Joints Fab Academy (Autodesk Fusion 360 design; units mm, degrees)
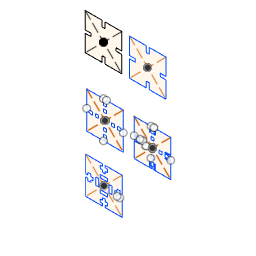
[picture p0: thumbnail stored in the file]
sketch "Joints Fab Academy"
  line L1 (132.7667, 45.561) -> (132.7667, 38.008)
  line L2 (132.0608, 36.2433) -> (132.2373, 36.4551)
  line L3 (123.5373, 64.2908) -> (123.8903, 64.3614)
  line L4 (132.4138, 36.7021) -> (132.555, 36.9139)
  line L5 (120.802, 48.8786) -> (120.802, 48.1374)
  line L6 (120.802, 48.1374) -> (116.9903, 48.1374)
  line L7 (127.8608, 48.0315) -> (123.202, 48.7727)
  line L8 (116.9903, 50.2904) -> (113.9903, 50.2904)
  line L9 (134.8314, 64.8202) -> (134.8314, 64.9614)
  line L10 (113.9903, 50.2904) -> (113.9903, 53.608)
  line L11 (122.9197, 28.1963) -> (122.7785, 28.3374)
  line L12 (123.0608, 28.0551) -> (122.9197, 28.1963)
  line L13 (123.1667, 27.8786) -> (123.0608, 28.0551)
  line L14 (116.9903, 24.3492) -> (116.9903, 26.0433)
  line L15 (132.2373, 36.4551) -> (132.4138, 36.7021)
  line L16 (122.5314, 34.6904) -> (121.9314, 34.6551)
  line L17 (113.0902, 73.8555) -> (113.0902, 81.2672)
  line L18 (115.3844, 83.8084) -> (115.6314, 83.8084)
  line L19 (125.1255, 84.7261) -> (125.1255, 84.6908)
  line L20 (125.055, 84.7261) -> (125.1255, 84.7261)
  line L21 (124.8785, 84.7614) -> (125.055, 84.7261)
  line L22 (118.0314, 83.8084) -> (122.9373, 84.5849)
  line L23 (116.9903, 29.961) -> (113.9903, 29.961)
  line L24 (131.1432, 35.6786) -> (131.3903, 35.7845)
  line L25 (132.7667, 37.7257) -> (132.7667, 38.008)
  line L26 (130.3314, 35.5374) -> (130.6138, 35.5374)
  line L27 (116.9903, 33.2786) -> (116.9903, 35.4316)
  line L28 (123.202, 34.7963) -> (122.5314, 34.6904)
  line L29 (135.4667, 80.6672) -> (135.4314, 80.7378)
  line L30 (135.4667, 80.5614) -> (135.4667, 80.6672)
  line L31 (135.0079, 81.5849) -> (134.9373, 81.8319)
  line L32 (135.0785, 81.3731) -> (135.0079, 81.5849)
  line L33 (135.2903, 80.9496) -> (135.0785, 81.3731)
  line L34 (135.4314, 80.7378) -> (135.2903, 80.9496)
  line L35 (132.5373, 80.632) -> (132.6432, 80.7378)
  line L36 (132.3961, 80.5614) -> (132.5373, 80.632)
  line L37 (133.702, 89.7378) -> (133.7373, 89.5614)
  line L38 (135.2197, 80.279) -> (135.3255, 80.3143)
  line L39 (135.1138, 80.279) -> (135.2197, 80.279)
  line L40 (135.0432, 80.3143) -> (135.1138, 80.279)
  line L41 (134.9373, 80.3849) -> (135.0432, 80.3143)
  line L42 (113.9903, 33.2786) -> (113.9903, 29.961)
  line L43 (122.5314, 48.8433) -> (121.9314, 48.9139)
  line L44 (132.7667, 45.8433) -> (132.7667, 45.561)
  line L45 (123.202, 48.7727) -> (122.5314, 48.8433)
  line L46 (116.9903, 50.2904) -> (116.9903, 48.1374)
  line L47 (116.9903, 59.2198) -> (116.9903, 57.5257)
  line L48 (132.255, 74.5966) -> (132.1138, 74.632)
  line L49 (135.2903, 74.1731) -> (135.4314, 74.3849)
  line L50 (132.7314, 46.1257) -> (132.7667, 45.8433)
  line L51 (121.9314, 48.9139) -> (121.5079, 48.9492)
  line L52 (135.1138, 61.8202) -> (134.8314, 61.8202)
  line L53 (131.8314, 65.632) -> (131.8314, 65.7731)
  line L54 (121.1197, 48.9139) -> (120.802, 48.8786)
  line L55 (130.3314, 35.5374) -> (127.8608, 35.5374)
  line L56 (123.0079, 70.5378) -> (122.9373, 70.5378)
  line L57 (134.902, 74.6672) -> (134.8667, 74.5966)
  line L58 (136.4726, 24.3492) -> (136.4726, 59.2198)
  line L59 (136.4726, 59.2198) -> (116.9903, 59.2198)
  line L60 (113.1255, 73.5731) -> (113.0902, 73.8555)
  line L61 (121.5079, 48.9492) -> (121.1197, 48.9139)
  line L62 (137.3726, 91.0084) -> (137.3726, 90.7261)
  line L63 (123.2726, 27.1021) -> (123.3079, 27.3139)
  line L64 (116.9903, 26.0433) -> (122.0373, 26.0433)
  line L65 (123.2373, 26.9257) -> (123.2726, 27.1021)
  line L66 (123.1667, 26.7139) -> (123.2373, 26.9257)
  line L67 (122.9197, 26.3963) -> (123.0608, 26.5727)
  line L68 (122.7785, 26.2904) -> (122.9197, 26.3963)
  line L69 (123.0608, 26.5727) -> (123.1667, 26.7139)
  line L70 (131.3903, 35.7845) -> (131.6373, 35.9257)
  line L71 (130.8608, 35.608) -> (131.1432, 35.6786)
  line L72 (136.4726, 24.3492) -> (116.9903, 24.3492)
  line L73 (132.7314, 37.4433) -> (132.7667, 37.7257)
  line L74 (131.3903, 47.7845) -> (131.6373, 47.6433)
  line L75 (123.2373, 27.7021) -> (123.1667, 27.8786)
  line L76 (132.555, 46.6198) -> (132.6608, 46.3727)
  line L77 (120.802, 35.4316) -> (116.9903, 35.4316)
  line L78 (132.555, 36.9139) -> (132.6608, 37.1963)
  line L79 (122.4255, 28.5139) -> (122.2138, 28.5492)
  line L80 (122.2138, 28.5492) -> (122.0373, 28.5845)
  line L81 (120.802, 34.6551) -> (120.802, 35.4316)
  line L82 (123.2726, 27.4904) -> (123.2373, 27.7021)
  line L83 (123.3079, 27.3139) -> (123.2726, 27.4904)
  line L84 (126.7314, 15.6908) -> (123.7314, 15.6908)
  line L85 (131.8844, 21.3025) -> (131.8844, -16.321)
  line L86 (118.5785, 21.3025) -> (131.8844, 21.3025)
  line L87 (118.5785, -16.321) -> (118.5785, 21.3025)
  line L88 (131.8844, -16.321) -> (118.5785, -16.321)
  line L89 (116.9903, 54.9845) -> (116.9903, 53.608)
  line L90 (122.2138, 54.9845) -> (122.0373, 54.9845)
  line L91 (122.4255, 55.0551) -> (122.2138, 54.9845)
  line L92 (122.602, 55.1257) -> (122.4255, 55.0551)
  line L93 (122.7785, 55.2315) -> (122.602, 55.1257)
  line L94 (122.9197, 55.3727) -> (122.7785, 55.2315)
  line L95 (116.9903, 53.608) -> (113.9903, 53.608)
  line L96 (126.7314, -13.2151) -> (123.7314, -13.2151)
  line L97 (123.7314, -13.2151) -> (123.7314, -10.7092)
  line L98 (116.9903, 54.9845) -> (122.0373, 54.9845)
  line L99 (123.0608, 55.5139) -> (122.9197, 55.3727)
  line L100 (123.1667, 55.6904) -> (123.0608, 55.5139)
  line L101 (123.2373, 55.8668) -> (123.1667, 55.6904)
  line L102 (123.2726, 56.0433) -> (123.2373, 55.8668)
  line L103 (123.3079, 56.2551) -> (123.2726, 56.0433)
  line L104 (123.2726, 56.4668) -> (123.3079, 56.2551)
  line L105 (123.2373, 56.6433) -> (123.2726, 56.4668)
  line L106 (123.1667, 56.8198) -> (123.2373, 56.6433)
  line L107 (123.0608, 56.9962) -> (123.1667, 56.8198)
  line L108 (122.9197, 57.1374) -> (123.0608, 56.9962)
  line L109 (122.7785, 57.2786) -> (122.9197, 57.1374)
  line L110 (122.602, 57.3845) -> (122.7785, 57.2786)
  line L111 (122.4255, 57.4551) -> (122.602, 57.3845)
  line L112 (122.2138, 57.5257) -> (122.4255, 57.4551)
  line L113 (122.0373, 57.5257) -> (122.2138, 57.5257)
  line L114 (123.7314, -10.7092) -> (126.7314, -10.7092)
  line L115 (126.7314, -10.7092) -> (126.7314, -13.2151)
  line L116 (123.7314, 15.6908) -> (123.7314, 18.1614)
  line L117 (123.7314, 18.1614) -> (126.7314, 18.1614)
  line L118 (126.7314, 18.1614) -> (126.7314, 15.6908)
  line L119 (116.9903, 57.5257) -> (122.0373, 57.5257)
  line L120 (122.0373, 26.0433) -> (122.2138, 26.0433)
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sketch "Sketch2"
  line L1 (-25, -25) -> (25, 25)
  line L2 (25, -25) -> (-25, 25)
  line L3 (-2, 17) -> (2, 17)
  line L4 (-2, 25) -> (-2, 17)
  line L5 (2, 17) -> (2, 25)
  line L6 (17, -2) -> (25, -2)
  line L7 (17, 2) -> (17, -2)
  line L8 (25, 2) -> (17, 2)
  line L9 (-25, -2) -> (-17, -2)
  line L10 (-17, 2) -> (-25, 2)
  line L11 (-17, -2) -> (-17, 2)
  line L12 (-2, -17) -> (2, -17)
  line L13 (-2, -25) -> (-2, -17)
  line L14 (2, -17) -> (2, -25)
  line L15 (25, -2) -> (25, -25)
  line L16 (25, 25) -> (25, 2)
  line L17 (2, 25) -> (25, 25)
  line L18 (-25, 25) -> (-2, 25)
  line L19 (-25, 2) -> (-25, 25)
  line L20 (-25, -25) -> (-25, -2)
  line L21 (-2, -25) -> (-25, -25)
  line L22 (25, -25) -> (2, -25)
  line L23 (85.5, -25) -> (62.5, -25)
  line L24 (58.5, -25) -> (35.5, -25)
  line L25 (35.5, 2) -> (35.5, 25)
  line L26 (35.5, 25) -> (58.5, 25)
  line L27 (62.5, 25) -> (85.5, 25)
  line L28 (85.5, 25) -> (85.5, 2)
  line L29 (85.5, -2) -> (85.5, -25)
  line L30 (62.5, -17) -> (62.5, -25)
  line L31 (58.5, -25) -> (58.5, -17)
  line L32 (58.5, -17) -> (62.5, -17)
  line L33 (43.5, 2) -> (35.5, 2)
  line L34 (35.5, -2) -> (43.5, -2)
  line L35 (85.5, 2) -> (77.5, 2)
  line L36 (77.5, 2) -> (77.5, -2)
  line L37 (77.5, -2) -> (85.5, -2)
  line L38 (62.5, 17) -> (62.5, 25)
  line L39 (58.5, 25) -> (58.5, 17)
  line L40 (58.5, 17) -> (62.5, 17)
  line L41 (85.5, -25) -> (35.5, 25)
  line L42 (35.5, -25) -> (85.5, 25)
  line L43 (35.5, -25) -> (35.5, -2)
  line L44 (43.5, -2) -> (43.5, 2)
  line L45 (-23, -67) -> (0, -67)
  line L46 (-23, -117) -> (-23, -94)
  line L47 (0, -75) -> (4, -75)
  line L48 (-19, -94) -> (-15, -94)
  line L49 (23, -90) -> (19, -90)
  line L50 (27, -94) -> (27, -117)
  line L51 (4, -109) -> (4, -113)
  line L52 (19, -90) -> (19, -94)
  line L53 (4, -75) -> (4, -71)
  line L54 (27, -117) -> (-23, -67)
  line L55 (0, -113) -> (0, -109)
  line L56 (0, -109) -> (4, -109)
  line L57 (4, -67) -> (27, -67)
  line L58 (27, -67) -> (27, -90)
  line L59 (-15, -90) -> (-19, -90)
  line L60 (-15, -94) -> (-15, -90)
  line L61 (-23, -117) -> (27, -67)
  line L62 (0, -117) -> (-23, -117)
  line L63 (27, -117) -> (4, -117)
  line L64 (0, -71) -> (0, -75)
  line L65 (19, -94) -> (23, -94)
  line L66 (-23, -90) -> (-23, -67)
  line L67 (4, -79) -> (0, -79)
  line L68 (4, -83) -> (4, -79)
  line L69 (0, -83) -> (4, -83)
  line L70 (0, -79) -> (0, -83)
  line L71 (11, -90) -> (15, -90)
  line L72 (11, -94) -> (11, -90)
  line L73 (15, -94) -> (11, -94)
  line L74 (15, -90) -> (15, -94)
  line L75 (4, -105) -> (0, -105)
  line L76 (4, -101) -> (4, -105)
  line L77 (0, -101) -> (4, -101)
  line L78 (0, -105) -> (0, -101)
  line L79 (-7, -90) -> (-11, -90)
  line L80 (-7, -94) -> (-7, -90)
  line L81 (-11, -94) -> (-7, -94)
  line L82 (-11, -90) -> (-11, -94)
  line L83 (25.5, -172) -> (25.5, -195)
  line L84 (-24.5, -145) -> (-1.5, -145)
  line L85 (-24.5, -195) -> (25.5, -145)
  line L86 (-24.5, -168) -> (-24.5, -145)
  line L87 (-14.5, -172) -> (-14.5, -168)
  line L88 (-1.5, -195) -> (-24.5, -195)
  line L89 (25.5, -195) -> (-24.5, -145)
  line L90 (2.5, -145) -> (25.5, -145)
  line L91 (25.5, -195) -> (2.5, -195)
  line L92 (-1.5, -155) -> (2.5, -155)
  line L93 (-24.5, -195) -> (-24.5, -172)
  line L94 (-1.5, -185) -> (2.5, -185)
  line L95 (25.5, -145) -> (25.5, -168)
  line L96 (15.5, -168) -> (15.5, -172)
  line L97 (-4.5, -152) -> (-4.5, -148)
  line L98 (5.5, -148) -> (5.5, -152)
  line L99 (-4.5, -159) -> (5.5, -159)
  line L100 (5.5, -163) -> (-4.5, -163)
  line L101 (-4.5, -163) -> (-4.5, -159)
  line L102 (5.5, -159) -> (5.5, -163)
  line L103 (-4.5, -177) -> (5.5, -177)
  line L104 (-4.5, -181) -> (-4.5, -177)
  line L105 (5.5, -181) -> (-4.5, -181)
  line L106 (5.5, -177) -> (5.5, -181)
  line L107 (5.5, -188) -> (5.5, -192)
  line L108 (-4.5, -192) -> (-4.5, -188)
  line L109 (2.5, -192) -> (2.5, -195)
  line L110 (2.5, -185) -> (2.5, -188)
  line L111 (2.5, -188) -> (5.5, -188)
  line L112 (-4.5, -188) -> (-1.5, -188)
  line L113 (-1.5, -188) -> (-1.5, -185)
  line L114 (-1.5, -195) -> (-1.5, -192)
  line L115 (-1.5, -192) -> (-4.5, -192)
  line L116 (5.5, -192) -> (2.5, -192)
  line L117 (2.5, -148) -> (5.5, -148)
  line L118 (-4.5, -148) -> (-1.5, -148)
  line L119 (-1.5, -152) -> (-1.5, -155)
  line L120 (-1.5, -145) -> (-1.5, -148)
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  point P17 (2, 25)
  point P18 (-2, 25)
  point P8 (-2, 17)
  point P2 (25, 25)
  point P3 (-25, 25)
  point P26 (58.5, 25)
  point P33 (62.5, 25)
  point P40 (58.5, 17)
  point P35 (35.5, 25)
  point P36 (85.5, 25)
  point P48 (0, -67)
  point P55 (4, -67)
  point P62 (0, -75)
  point P57 (-23, -67)
  point P58 (27, -67)
  point P67 (0, -79)
  point P65 (19, -90)
  point P71 (15, -90)
  point P70 (0, -83)
  point P45 (4, -109)
  point P76 (4, -105)
  point P60 (-15, -90)
  point P79 (-11, -90)
  point P80 (-7, -90)
  point P77 (4, -101)
  point P86 (-1.5, -145)
  point P89 (2.5, -145)
  point P96 (-1.5, -155)
  point P85 (25.5, -145)
  point P93 (-24.5, -145)
  point P107 (-4.5, -152)
  point P108 (5.5, -152)
  point P106 (-4.5, -148)
  point P110 (5.5, -163)
  point P111 (-4.5, -163)
  point P109 (-4.5, -159)
  point P117 (5.5, -181)
  point P119 (-4.5, -181)
  point P113 (-4.5, -177)
  point P116 (5.5, -192)
  point P118 (-4.5, -192)
  point P115 (-4.5, -188)
  point P94 (-24.5, -195)
  point P105 (5.5, -148)
  point P97 (-1.5, -185)
  point P130 (18.5, -165)
  point P131 (18.5, -175)
  point P129 (22.5, -165)
  point P133 (7.5, -165)
  point P136 (7.5, -175)
  point P134 (11.5, -175)
  point P139 (-10.5, -165)
  point P144 (-10.5, -175)
  point P140 (-6.5, -175)
  point P145 (-21.5, -165)
  point P146 (-21.5, -175)
  point P143 (-17.5, -175)
  point P87 (-24.5, -168)
  point P72 (11, -90)
  point P101 (15.5, -168)
  point P103 (25.5, -168)
  point P126 (-1.5, -148)
  point P102 (-14.5, -168)
  point P148 (-21.5, -172)
  point P84 (2.5, -185)
  point P92 (2.5, -195)
  point P121 (2.5, -192)
  point P137 (22.5, -173.5)
  point P138 (18.5, -173.5)
  point P152 (22.5, -168)
  point P162 (0, -67)
  point P165 (4, -67)
  point P181 (0, -75)
  point P161 (27, -67)
  point P169 (-23, -67)
  point P160 (0, -79)
  point P171 (15, -90)
  point P188 (19, -90)
  point P183 (0, -83)
  point P156 (4, -109)
  point P175 (4, -105)
  point P177 (-11, -90)
  point P189 (-15, -90)
  point P172 (-7, -90)
  point P174 (4, -101)
  point P180 (11, -90)
  point P200 (65, -67)
  point P203 (69, -67)
  point P246 (65, -75)
  point P199 (92, -67)
  point P207 (42, -67)
  point P198 (65, -79)
  point P209 (80, -90)
  point P253 (84, -90)
  point P248 (65, -83)
  point P212 (54, -90)
  point P254 (50, -90)
  point P210 (58, -90)
  point P245 (76, -90)
  point P231 (65, -67)
  point P235 (69, -67)
  point P241 (65, -75)
  point P222 (42, -67)
  point P237 (92, -67)
  point P230 (65, -79)
  point P223 (80, -90)
  point P232 (84, -90)
  point P242 (65, -83)
  point P215 (54, -90)
  point P233 (50, -90)
  point P240 (76, -90)
  point P258 (70, -67)
  point P259 (71, -67)
  point P262 (63, -67)
  point P263 (64, -67)
  point P266 (84, -89)
  point P269 (84, -88)
  point P270 (84, -95)
  point P273 (84, -96)
  point P274 (69.8629, -117)
  point P275 (70.8629, -117)
  point P278 (62.8629, -117)
  point P279 (63.8629, -117)
  point P282 (42, -88.9314)
  point P285 (42, -87.9314)
  point P286 (42, -95.0686)
  point P289 (42, -96.0686)
  point P219 (42, -89.9314)
  point P257 (64.8629, -117)
  point P213 (64.8629, -101)
  point P290 (68.8629, -101)
  point P292 (64.8629, -105)
  point P194 (68.8629, -109)
  point P291 (68.8629, -105)
  point P252 (92, -94)
  point P271 (92, -95)
  point P293 (1, -67)
  point P295 (0, -71)
  point P298 (4, -71)
  point P296 (3, -67)
  point P49 (-23, -90)
  point P299 (-19, -90)
  point P301 (-23, -91)
  point P155 (-23, -94)
  point P302 (-19, -94)
  point P304 (-23, -93)
  point P59 (27, -90)
  point P305 (23, -90)
  point P307 (27, -91)
  point P187 (27, -94)
  point P308 (23, -94)
  point P310 (27, -93)
  point P52 (0, -117)
  point P311 (1, -117)
  point P313 (0, -113)
  point P51 (4, -117)
  point P314 (3, -117)
  point P316 (4, -113)
  point P317 (66, -67)
  point P319 (65, -71)
  point P320 (68, -67)
  point P322 (69, -71)
  point P234 (92, -90)
  point P323 (88, -90)
  point P325 (92, -91)
  point P226 (92, -94)
  point P326 (88, -94)
  point P328 (92, -93)
  point P329 (65.8629, -117)
  point P331 (64.8629, -113)
  point P206 (68.8629, -117)
  point P332 (67.8629, -117)
  point P334 (68.8629, -113)
  point P201 (42, -90)
  point P335 (46, -90)
  point P337 (42, -91)
  point P193 (42, -94)
  point P340 (42, -93)
  point P338 (46, -94)
  dimension "d37" distance P17 P18 = 4
  dimension "d38" distance P8 P18 = 8
  dimension "d39" distance P2 P3 = 50
  dimension "d40" distance P26 P33 = 4
  dimension "d41" distance P26 P40 = 8
  dimension "d42" distance P35 P36 = 50
  dimension "d43" distance P48 P55 = 4
  dimension "d44" distance P48 P62 = 8
  dimension "d45" distance P57 P58 = 50
  dimension "d49" distance P62 P67 = 4
  dimension "d52" distance P65 P71 = 4
  dimension "d53" distance P67 P70 = 4
  dimension "d55" distance P45 P76 = 4
  dimension "d57" distance P60 P79 = 4
  dimension "d58" distance P79 P80 = 4
  dimension "d59" distance P76 P77 = 4
  dimension "d81" distance P86 P89 = 4
  dimension "d82" distance P86 P96 = 10
  dimension "d83" distance P85 P93 = 50
  dimension "d91" distance P107 P108 = 10
  dimension "d92" distance P106 P107 = 4
  dimension "d93" distance P110 P111 = 10
  dimension "d94" distance P109 P111 = 4
  dimension "d95" distance P96 P109 = 4
  dimension "d96" distance P117 P119 = 10
  dimension "d97" distance P113 P119 = 4
  dimension "d98" distance P116 P118 = 10
  dimension "d99" distance P115 P118 = 4
  dimension "d100" distance P93 P94 = 50
  dimension "d101" distance L90 P105 = 3
  dimension "d102" distance L88 P118 = 3
  dimension "d103" distance P97 P119 = 4
  dimension "d104" distance P130 P131 = 10
  dimension "d106" distance L95 P129 = 3
  dimension "d107" distance P133 P136 = 10
  dimension "d108" distance P134 P136 = 4
  dimension "d109" distance = 4
  dimension "d114" distance P139 P144 = 10
  dimension "d115" distance P140 P144 = 4
  dimension "d116" distance P145 P146 = 10
  dimension "d117" distance P143 P146 = 4
  dimension "d118" distance = 4
  dimension "d119" distance P87 P145 = 3
  dimension "d124" distance P71 P72 = 4
  dimension "d129" distance P101 P103 = 10
  dimension "d130" distance P106 P126 = 3
  dimension "d131" distance P87 P102 = 10
  dimension "d132" distance P146 P148 = 3
  dimension "d133" distance P84 P92 = 10
  dimension "d134" distance P116 P121 = 3
  dimension "d135" distance P137 P138 = 4
  dimension "d136" distance P129 P152 = 3
  dimension "d137" distance P162 P165 = 4
  dimension "d138" distance P162 P181 = 8
  dimension "d139" distance P161 P169 = 50
  dimension "d140" distance P160 P181 = 4
  dimension "d141" distance P171 P188 = 4
  dimension "d142" distance P160 P183 = 4
  dimension "d143" distance P156 P175 = 4
  dimension "d144" distance P177 P189 = 4
  dimension "d145" distance P172 P177 = 4
  dimension "d146" distance P174 P175 = 4
  dimension "d147" distance P171 P180 = 4
  dimension "d148" distance P200 P203 = 4
  dimension "d149" distance P200 P246 = 8
  dimension "d150" distance P199 P207 = 50
  dimension "d151" distance P198 P246 = 4
  dimension "d152" distance P209 P253 = 4
  dimension "d153" distance P198 P248 = 4
  dimension "d155" distance P212 P254 = 4
  dimension "d156" distance P210 P212 = 4
  dimension "d158" distance P209 P245 = 4
  dimension "d159" distance P231 P235 = 4
  dimension "d160" distance P231 P241 = 8
  dimension "d161" distance P222 P237 = 50
  dimension "d162" distance P230 P241 = 4
  dimension "d163" distance P223 P232 = 4
  dimension "d164" distance P230 P242 = 4
  dimension "d166" distance P215 P233 = 4
  dimension "d169" distance P223 P240 = 4
  dimension "d170" distance P258 P259 = 1
  dimension "d171" distance P235 P258 = 1
  dimension "d172" distance P262 P263 = 1
  dimension "d173" distance P266 P269 = 1
  dimension "d174" distance P270 P273 = 1
  dimension "d175" distance P274 P275 = 1
  dimension "d176" distance P278 P279 = 1
  dimension "d177" distance P282 P285 = 1
  dimension "d178" distance P286 P289 = 1
  dimension "d180" distance P219 P282 = 1
  dimension "d182" distance P257 P279 = 1
  dimension "d183" distance P213 P290 = 4
  dimension "d184" distance P213 P292 = 4
  dimension "d185" distance P194 P291 = 4
  dimension "d186" distance P252 P271 = 1
  dimension "d192" distance P48 P293 = 1
  dimension "d193" distance P48 P295 = 4
  dimension "d194" distance P55 P298 = 4
  dimension "d195" distance P55 P296 = 1
  dimension "d196" distance P49 P299 = 4
  dimension "d197" distance P49 P301 = 1
  dimension "d198" distance P155 P302 = 4
  dimension "d199" distance P155 P304 = 1
  dimension "d200" distance P59 P305 = 4
  dimension "d201" distance P59 P307 = 1
  dimension "d202" distance P187 P308 = 4
  dimension "d203" distance P187 P310 = 1
  dimension "d204" distance P52 P311 = 1
  dimension "d205" distance P52 P313 = 4
  dimension "d206" distance P51 P314 = 1
  dimension "d207" distance P51 P316 = 4
  dimension "d208" distance P200 P317 = 1
  dimension "d209" distance P200 P319 = 4
  dimension "d210" distance P203 P320 = 1
  dimension "d211" distance P203 P322 = 4
  dimension "d212" distance P234 P323 = 4
  dimension "d213" distance P234 P325 = 1
  dimension "d214" distance P226 P326 = 4
  dimension "d215" distance P226 P328 = 1
  dimension "d216" distance P257 P329 = 1
  dimension "d217" distance P257 P331 = 4
  dimension "d218" distance P206 P332 = 1
  dimension "d219" distance P206 P334 = 4
  dimension "d220" distance P201 P335 = 4
  dimension "d221" distance P201 P337 = 1
  dimension "d222" distance P193 P340 = 1
  dimension "d223" distance P193 P338 = 4
extrude "Extrude2" new body sketch "Sketch2" blind 4
extrude "Extrude1" new body sketch "Sketch2" blind 4
chamfer "Chamfer1" distance 1.5
extrude "Extrude3" new body sketch "Sketch2" blind 4
chamfer "Chamfer2" distance 1.5
chamfer "Chamfer3" distance 1.5
sketch "Sketch4"
  line L1 (5.5, -177) -> (-4.5, -177)
  line L2 (-4.5, -177) -> (-4.5, -181)
  line L3 (-4.5, -181) -> (5.5, -181)
  line L4 (5.5, -181) -> (5.5, -177)
  line L5 (-6.5, -175) -> (-6.5, -165)
  line L6 (-6.5, -165) -> (-10.5, -165)
  line L7 (-10.5, -165) -> (-10.5, -175)
  line L8 (-10.5, -175) -> (-6.5, -175)
  line L9 (11.5, -175) -> (11.5, -165)
  line L10 (11.5, -165) -> (7.5, -165)
  line L11 (7.5, -165) -> (7.5, -175)
  line L12 (7.5, -175) -> (11.5, -175)
  line L13 (5.5, -159) -> (-4.5, -159)
  line L14 (-4.5, -159) -> (-4.5, -163)
  line L15 (-4.5, -163) -> (5.5, -163)
  line L16 (5.5, -163) -> (5.5, -159)
  line L17 (15.5, -172) -> (18.5, -172)
  line L18 (18.5, -175) -> (18.5, -172)
  line L19 (22.5, -175) -> (18.5, -175)
  line L20 (22.5, -172) -> (22.5, -175)
  line L21 (22.5, -172) -> (25.5, -172)
  line L22 (25.5, -172) -> (25.5, -195)
  line L23 (25.5, -195) -> (2.5, -195)
  line L24 (2.5, -192) -> (2.5, -195)
  line L25 (5.5, -192) -> (2.5, -192)
  line L26 (5.5, -188) -> (5.5, -192)
  line L27 (2.5, -188) -> (5.5, -188)
  line L28 (2.5, -185) -> (2.5, -188)
  line L29 (-1.5, -185) -> (2.5, -185)
  line L30 (-1.5, -188) -> (-1.5, -185)
  line L31 (-4.5, -188) -> (-1.5, -188)
  line L32 (-4.5, -192) -> (-4.5, -188)
  line L33 (-1.5, -192) -> (-4.5, -192)
  line L34 (-1.5, -195) -> (-1.5, -192)
  line L35 (-1.5, -195) -> (-24.5, -195)
  line L36 (-24.5, -195) -> (-24.5, -172)
  line L37 (-24.5, -172) -> (-21.5, -172)
  line L38 (-21.5, -175) -> (-21.5, -172)
  line L39 (-17.5, -175) -> (-21.5, -175)
  line L40 (-17.5, -172) -> (-17.5, -175)
  line L41 (-17.5, -172) -> (-14.5, -172)
  line L42 (-14.5, -172) -> (-14.5, -168)
  line L43 (-14.5, -168) -> (-17.5, -168)
  line L44 (-17.5, -165) -> (-17.5, -168)
  line L45 (-21.5, -165) -> (-17.5, -165)
  line L46 (-21.5, -168) -> (-21.5, -165)
  line L47 (-21.5, -168) -> (-24.5, -168)
  line L48 (-24.5, -168) -> (-24.5, -145)
  line L49 (-24.5, -145) -> (-1.5, -145)
  line L50 (-1.5, -145) -> (-1.5, -148)
  line L51 (-4.5, -148) -> (-1.5, -148)
  line L52 (-4.5, -152) -> (-4.5, -148)
  line L53 (-1.5, -152) -> (-4.5, -152)
  line L54 (-1.5, -152) -> (-1.5, -155)
  line L55 (-1.5, -155) -> (2.5, -155)
  line L56 (2.5, -155) -> (2.5, -152)
  line L57 (5.5, -152) -> (2.5, -152)
  line L58 (5.5, -148) -> (5.5, -152)
  line L59 (2.5, -148) -> (5.5, -148)
  line L60 (2.5, -148) -> (2.5, -145)
  line L61 (2.5, -145) -> (25.5, -145)
  line L62 (25.5, -145) -> (25.5, -168)
  line L63 (25.5, -168) -> (22.5, -168)
  line L64 (22.5, -165) -> (22.5, -168)
  line L65 (18.5, -165) -> (22.5, -165)
  line L66 (18.5, -168) -> (18.5, -165)
  line L67 (18.5, -168) -> (15.5, -168)
  line L68 (15.5, -168) -> (15.5, -172)
  line L69 (27, -89.5) -> (25.5, -91)
  line L70 (27, -67) -> (27, -89.5)
  line L71 (-7, -90) -> (-11, -90)
  line L72 (-11, -90) -> (-11, -94)
  line L73 (-11, -94) -> (-7, -94)
  line L74 (-7, -94) -> (-7, -90)
  line L75 (0, -79) -> (0, -83)
  line L76 (0, -83) -> (4, -83)
  line L77 (4, -83) -> (4, -79)
  line L78 (4, -79) -> (0, -79)
  line L79 (15, -94) -> (15, -90)
  line L80 (15, -90) -> (11, -90)
  line L81 (11, -90) -> (11, -94)
  line L82 (11, -94) -> (15, -94)
  line L83 (4, -105) -> (4, -101)
  line L84 (4, -101) -> (0, -101)
  line L85 (0, -101) -> (0, -105)
  line L86 (0, -105) -> (4, -105)
  line L87 (25.5, -91) -> (23, -91)
  line L88 (23, -91) -> (23, -90)
  line L89 (23, -90) -> (19, -90)
  line L90 (19, -90) -> (19, -94)
  line L91 (19, -94) -> (23, -94)
  line L92 (23, -93) -> (23, -94)
  line L93 (25.5, -93) -> (23, -93)
  line L94 (25.5, -93) -> (27, -94.5)
  line L95 (27, -94.5) -> (27, -117)
  line L96 (27, -117) -> (4.5, -117)
  line L97 (4.5, -117) -> (3, -115.5)
  line L98 (3, -113) -> (3, -115.5)
  line L99 (4, -113) -> (3, -113)
  line L100 (4, -109) -> (4, -113)
  line L101 (0, -109) -> (4, -109)
  line L102 (0, -113) -> (0, -109)
  line L103 (0, -113) -> (1, -113)
  line L104 (1, -113) -> (1, -115.5)
  line L105 (1, -115.5) -> (-0.5, -117)
  line L106 (-0.5, -117) -> (-23, -117)
  line L107 (-23, -117) -> (-23, -94.5)
  line L108 (-23, -94.5) -> (-21.5, -93)
  line L109 (-21.5, -93) -> (-19, -93)
  line L110 (-19, -93) -> (-19, -94)
  line L111 (-19, -94) -> (-15, -94)
  line L112 (-15, -94) -> (-15, -90)
  line L113 (-15, -90) -> (-19, -90)
  line L114 (-19, -91) -> (-19, -90)
  line L115 (-21.5, -91) -> (-19, -91)
  line L116 (-21.5, -91) -> (-23, -89.5)
  line L117 (-23, -89.5) -> (-23, -67)
  line L118 (-0.5, -67) -> (-23, -67)
  line L119 (-0.5, -67) -> (1, -68.5)
  line L120 (1, -71) -> (1, -68.5)
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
